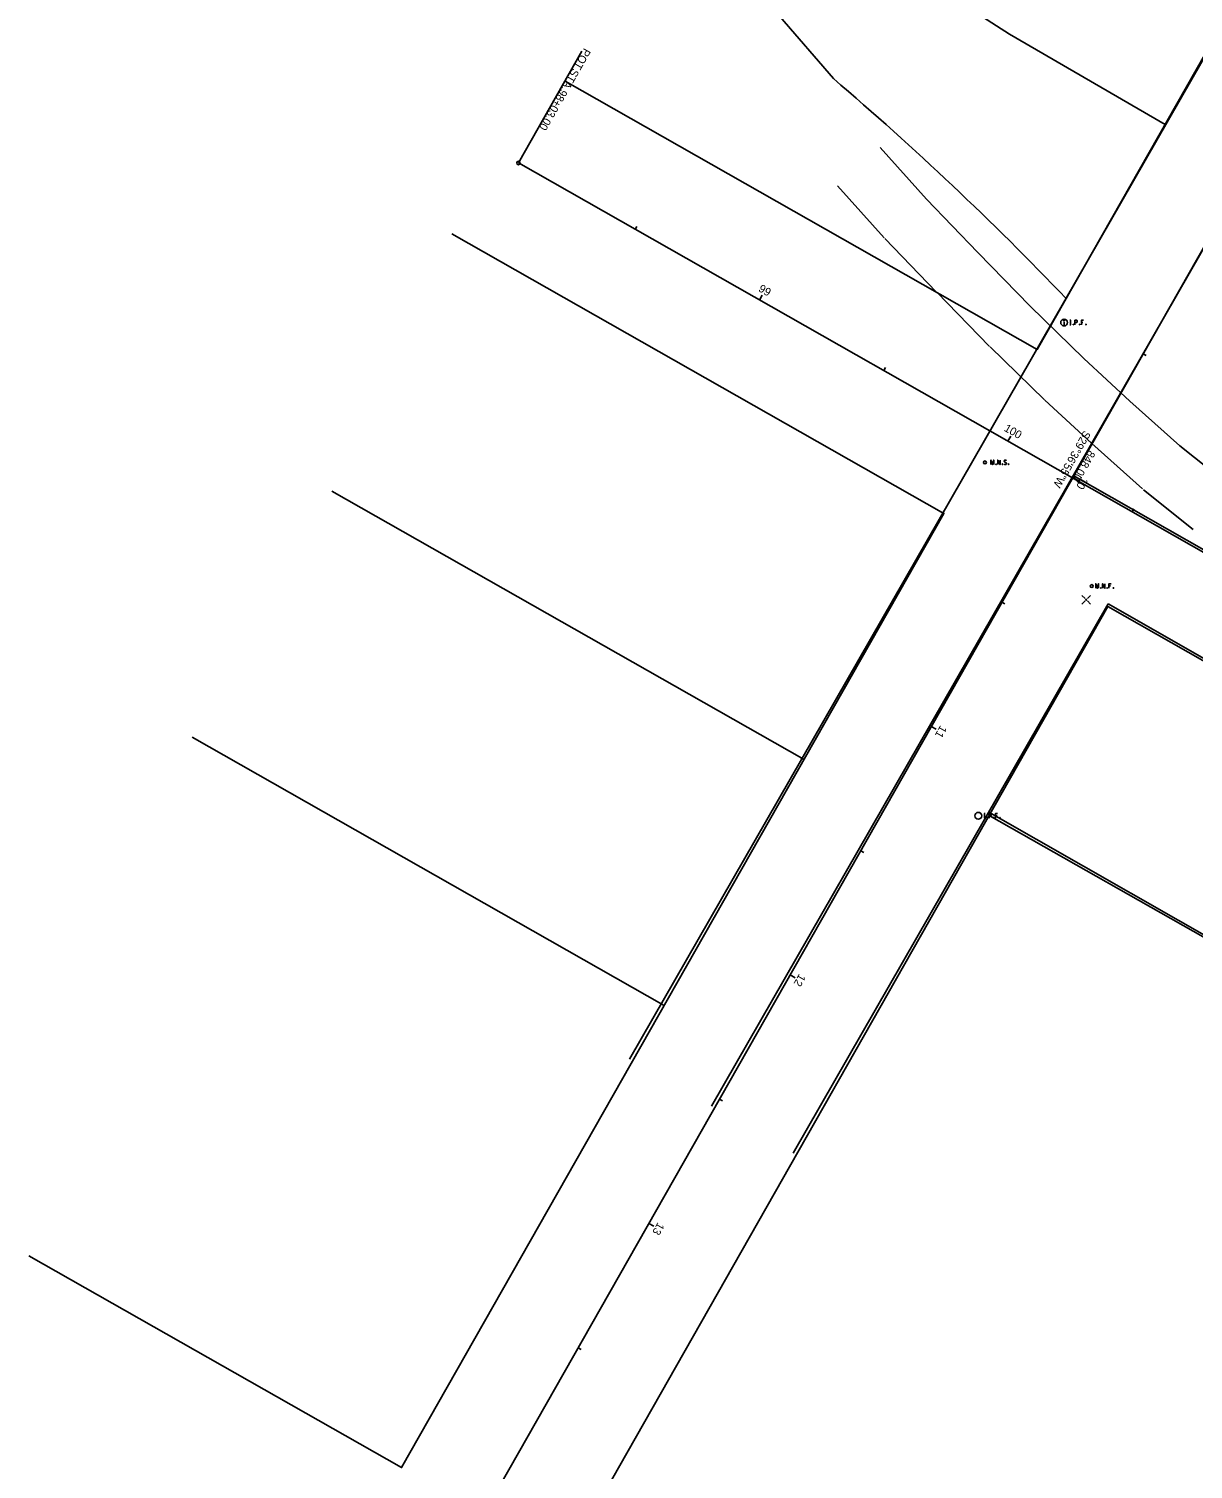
# Model space of a CAD drawing. Extents: x 119320 to 120701, y 385020 to 386199.
# Drawn here: x 119320 to 119728, y 385433 to 385937 of the extents above; entities that cross this region are included whole.
import ezdxf

# ---------------------------------------------------------------- set-up
doc = ezdxf.new("R2010")
doc.units = 0
for name, color, linetype in [('DV_X_Property_Line', 7, 'Continuous'), ('RW_X_CL', 7, 'Continuous'), ('RW_X_CL_100_Bearings', 7, 'Continuous'), ('RW_X_CL_100_Cardinal_Points', 7, 'Continuous'), ('RW_X_CL_100_Distances', 7, 'Continuous'), ('RW_X_CL_100_Stations', 7, 'Continuous'), ('RW_X_Esmt_RR', 7, 'Continuous'), ('RW_X_Fee_RW', 7, 'Continuous'), ('SC_Scratch1', 7, 'Continuous'), ('SV_P_Control_Cells_Set', 7, 'Continuous'), ('SV_X_Control_Cells_Found', 7, 'Continuous'), ('SV_X_Mon_Cells_Found', 7, 'Continuous')]:
    doc.layers.add(name, color=color, linetype=linetype)

msp = doc.modelspace()

# ---------------------------------------------------------------- linework, layer by layer
at = {"layer": 'DV_X_Property_Line'}
for p, q in [((119591.63, 385681.57), (119426.46, 385775.46)), ((119542.71, 385595.5), (119377.53, 385689.39)), ((119771.7, 385596.46), (119656.42, 385661.99))]:
    msp.add_line(p, q, dxfattribs=at)
msp.add_lwpolyline([(119601.86, 385919.77), (119583.12, 385941.5), (119603.33, 385973.97), (119663.5, 385935.28), (119717.9, 385903.69)], dxfattribs=at)
msp.add_arc((118870.1, 385063.6), 1126.28, 43.77787, 49.47989, dxfattribs=at)
at = {"layer": 'RW_X_CL'}
for p, q in [((119897.55, 386152.97), (119478.5, 385415.75)), ((119491.69, 385890.22), (120488.85, 385323.4))]:
    msp.add_line(p, q, dxfattribs=at)
at = {"layer": 'RW_X_CL_100_Cardinal_Points'}
msp.add_line((119491.69, 385890.22), (119513.92, 385929.34), dxfattribs=at)
msp.add_circle((119491.69, 385890.22), 0.6, dxfattribs=at)
at = {"layer": 'RW_X_CL_100_Stations'}
for p, q in [((119532.55, 385866.99), (119533.14, 385868.03)), ((119576.01, 385842.28), (119577, 385844.02)), ((119710.26, 385823.48), (119711.31, 385822.89)), ((119619.48, 385817.57), (119620.08, 385818.62)), ((119662.95, 385792.86), (119663.94, 385794.6)), ((119685.55, 385780.02), (119687.29, 385779.03)), ((119706.42, 385768.16), (119707.01, 385769.2)), ((119660.85, 385736.55), (119661.89, 385735.95)), ((119636.14, 385693.08), (119637.88, 385692.09)), ((119611.43, 385649.61), (119612.47, 385649.02)), ((119586.72, 385606.14), (119588.46, 385605.15)), ((119562.01, 385562.67), (119563.05, 385562.08)), ((119537.3, 385519.21), (119539.04, 385518.22)), ((119512.59, 385475.74), (119513.64, 385475.15))]:
    msp.add_line(p, q, dxfattribs=at)
at = {"layer": 'RW_X_Esmt_RR'}
for p, q in [((119618.22, 385895.61), (119634.45, 385877.51)), ((119603.33, 385882.25), (119619.68, 385864.02)), ((119634.45, 385877.51), (119652.36, 385858.93)), ((119619.93, 385863.76), (119637.98, 385845.03)), ((119652.36, 385858.93), (119670.73, 385840.1)), ((119638.02, 385844.99), (119656.51, 385826.04)), ((119670.73, 385840.1), (119689.55, 385821.79)), ((119656.69, 385825.86), (119675.69, 385807.36)), ((119689.55, 385821.79), (119705.64, 385806.91)), ((119675.88, 385807.19), (119692.13, 385792.17)), ((119705.64, 385806.91), (119723.13, 385791.28)), ((119692.25, 385792.06), (119710, 385776.19)), ((119723.13, 385791.28), (119740.18, 385777.58)), ((119710.4, 385775.85), (119727.7, 385761.95))]:
    msp.add_line(p, q, dxfattribs=at)
at = {"layer": 'RW_X_Fee_RW'}
for points in [[(119507.99, 385918.9), (119673.17, 385825.01), (119869.11, 386169.71), (119816.95, 386199.36)], [(119468.42, 385865.48), (119640.56, 385767.63), (119450.79, 385433.8), (119320.39, 385507.92)], [(119507.18, 385399.44), (119697.94, 385735.02), (120042.2, 385539.33), (119851.45, 385203.75), (119507.18, 385399.44)]]:
    msp.add_lwpolyline(points, dxfattribs=at)
at = {"layer": 'SC_Scratch1'}
for p, q in [((119530.56, 385576.63), (119762.43, 385980.86)), ((119559.19, 385560.21), (119791.06, 385964.44)), ((119685.77, 385780.89), (120087.8, 385551.87)), ((119587.81, 385543.79), (119698.02, 385735.93)), ((119698.02, 385735.93), (119813.24, 385670.29)), ((119656.23, 385663.06), (119828.3, 385565.04))]:
    msp.add_line(p, q, dxfattribs=at)
at = {"layer": 'SV_P_Control_Cells_Set'}
for points in [[(119657, 385784.69), (119657, 385786.29), (119657.51, 385784.69), (119657.99, 385786.29), (119657.99, 385784.69)], [(119659.37, 385784.69), (119659.37, 385786.29), (119660.2, 385784.69), (119660.2, 385786.29)], [(119662.35, 385786.18), (119662.33, 385786.21), (119662.29, 385786.23), (119662.19, 385786.27), (119662.07, 385786.29), (119661.98, 385786.29), (119661.95, 385786.29), (119661.81, 385786.26), (119661.69, 385786.18), (119661.61, 385786.08), (119661.59, 385785.98), (119661.59, 385785.9), (119661.61, 385785.8), (119661.7, 385785.71), (119662.3, 385785.34), (119662.36, 385785.29), (119662.38, 385785.24), (119662.4, 385785.16), (119662.4, 385785.08), (119662.39, 385785.01), (119662.38, 385784.96), (119662.36, 385784.89), (119662.34, 385784.84), (119662.31, 385784.81), (119662.28, 385784.77), (119662.25, 385784.74), (119662.2, 385784.72), (119662.17, 385784.71), (119662.07, 385784.69), (119661.92, 385784.69), (119661.82, 385784.72), (119661.68, 385784.81), (119661.59, 385784.88)], [(119658.77, 385784.91), (119658.82, 385784.91), (119658.85, 385784.88), (119658.89, 385784.83), (119658.89, 385784.77), (119658.85, 385784.72), (119658.82, 385784.69), (119658.77, 385784.69), (119658.73, 385784.72), (119658.7, 385784.77), (119658.7, 385784.83), (119658.73, 385784.88), (119658.77, 385784.91)], [(119660.98, 385784.91), (119661.04, 385784.91), (119661.07, 385784.88), (119661.1, 385784.83), (119661.1, 385784.77), (119661.07, 385784.72), (119661.04, 385784.69), (119660.98, 385784.69), (119660.95, 385784.72), (119660.91, 385784.77), (119660.91, 385784.83), (119660.95, 385784.88), (119660.98, 385784.91)], [(119663.16, 385784.91), (119663.22, 385784.91), (119663.25, 385784.88), (119663.28, 385784.83), (119663.28, 385784.77), (119663.25, 385784.72), (119663.22, 385784.69), (119663.16, 385784.69), (119663.13, 385784.72), (119663.1, 385784.77), (119663.1, 385784.83), (119663.13, 385784.88), (119663.16, 385784.91)]]:
    msp.add_lwpolyline(points, dxfattribs=at)
msp.add_circle((119654.91, 385785.49), 0.497, dxfattribs=at)
at = {"layer": 'SV_X_Control_Cells_Found'}
for p, q in [((119688.82, 385738.94), (119689.91, 385737.85)), ((119688.82, 385735.92), (119689.91, 385737.01)), ((119690.74, 385737.85), (119691.83, 385738.94)), ((119690.74, 385737.01), (119691.83, 385735.92))]:
    msp.add_line(p, q, dxfattribs=at)
for points in [[(119693.69, 385741.41), (119693.69, 385743.01), (119694.2, 385741.41), (119694.68, 385743.01), (119694.68, 385741.41)], [(119695.45, 385741.63), (119695.51, 385741.63), (119695.54, 385741.6), (119695.57, 385741.55), (119695.57, 385741.49), (119695.54, 385741.44), (119695.51, 385741.41), (119695.45, 385741.41), (119695.42, 385741.44), (119695.39, 385741.49), (119695.39, 385741.55), (119695.42, 385741.6), (119695.45, 385741.63)], [(119696.06, 385741.41), (119696.06, 385743.01), (119696.89, 385741.41), (119696.89, 385743.01)], [(119697.67, 385741.63), (119697.72, 385741.63), (119697.76, 385741.6), (119697.79, 385741.55), (119697.79, 385741.49), (119697.76, 385741.44), (119697.72, 385741.41), (119697.67, 385741.41), (119697.64, 385741.44), (119697.6, 385741.49), (119697.6, 385741.55), (119697.64, 385741.6), (119697.67, 385741.63)], [(119699.04, 385743.01), (119698.27, 385743.01), (119698.27, 385741.41)], [(119698.27, 385742.23), (119698.82, 385742.23)], [(119699.82, 385741.63), (119699.87, 385741.63), (119699.91, 385741.6), (119699.94, 385741.55), (119699.94, 385741.49), (119699.91, 385741.44), (119699.87, 385741.41), (119699.82, 385741.41), (119699.78, 385741.44), (119699.75, 385741.49), (119699.75, 385741.55), (119699.78, 385741.6), (119699.82, 385741.63)]]:
    msp.add_lwpolyline(points, dxfattribs=at)
for centre, radius in [((119692.25, 385742.22), 0.497), ((119690.33, 385737.44), 0.17)]:
    msp.add_circle(centre, radius, dxfattribs=at)
at = {"layer": 'SV_X_Mon_Cells_Found'}
msp.add_line((119682.61, 385834.53), (119682.61, 385833.65), dxfattribs=at)
for points in [[(119684.64, 385835.21), (119685, 385835.21)], [(119684.64, 385833.61), (119685, 385833.61)], [(119684.82, 385833.61), (119684.82, 385835.21)], [(119685.78, 385833.83), (119685.83, 385833.83), (119685.87, 385833.8), (119685.9, 385833.75), (119685.9, 385833.69), (119685.87, 385833.64), (119685.83, 385833.61), (119685.78, 385833.61), (119685.75, 385833.64), (119685.71, 385833.69), (119685.71, 385833.75), (119685.75, 385833.8), (119685.78, 385833.83)], [(119686.39, 385833.61), (119686.39, 385835.21), (119686.92, 385835.21), (119686.97, 385835.2), (119687.05, 385835.18), (119687.08, 385835.15), (119687.11, 385835.12), (119687.16, 385835.06), (119687.19, 385835), (119687.21, 385834.9), (119687.21, 385834.75), (119687.2, 385834.7), (119687.18, 385834.62), (119687.14, 385834.53), (119687.09, 385834.49), (119687.06, 385834.47), (119687, 385834.44), (119686.92, 385834.43), (119686.39, 385834.43)], [(119688.03, 385833.83), (119688.08, 385833.83), (119688.12, 385833.8), (119688.15, 385833.75), (119688.15, 385833.69), (119688.12, 385833.64), (119688.08, 385833.61), (119688.03, 385833.61), (119688, 385833.64), (119687.96, 385833.69), (119687.96, 385833.75), (119688, 385833.8), (119688.03, 385833.83)], [(119689.4, 385835.21), (119688.63, 385835.21), (119688.63, 385833.61)], [(119688.63, 385834.43), (119689.17, 385834.43)], [(119690.18, 385833.83), (119690.23, 385833.83), (119690.27, 385833.8), (119690.3, 385833.75), (119690.3, 385833.69), (119690.27, 385833.64), (119690.23, 385833.61), (119690.18, 385833.61), (119690.14, 385833.64), (119690.11, 385833.69), (119690.11, 385833.75), (119690.14, 385833.8), (119690.18, 385833.83)], [(119654.59, 385662.63), (119654.95, 385662.63)], [(119654.59, 385661.03), (119654.95, 385661.03)], [(119654.77, 385661.03), (119654.77, 385662.63)], [(119655.73, 385661.25), (119655.78, 385661.25), (119655.82, 385661.22), (119655.85, 385661.17), (119655.85, 385661.11), (119655.82, 385661.06), (119655.78, 385661.03), (119655.73, 385661.03), (119655.7, 385661.06), (119655.66, 385661.11), (119655.66, 385661.17), (119655.7, 385661.22), (119655.73, 385661.25)], [(119656.34, 385661.03), (119656.34, 385662.63), (119656.86, 385662.63), (119656.92, 385662.62), (119657, 385662.6), (119657.03, 385662.57), (119657.06, 385662.54), (119657.11, 385662.48), (119657.14, 385662.42), (119657.16, 385662.32), (119657.16, 385662.17), (119657.15, 385662.12), (119657.13, 385662.04), (119657.08, 385661.95), (119657.04, 385661.91), (119657.01, 385661.89), (119656.95, 385661.86), (119656.86, 385661.85), (119656.34, 385661.85)], [(119657.98, 385661.25), (119658.03, 385661.25), (119658.07, 385661.22), (119658.1, 385661.17), (119658.1, 385661.11), (119658.07, 385661.06), (119658.03, 385661.03), (119657.98, 385661.03), (119657.94, 385661.06), (119657.91, 385661.11), (119657.91, 385661.17), (119657.94, 385661.22), (119657.98, 385661.25)], [(119659.34, 385662.63), (119658.58, 385662.63), (119658.58, 385661.03)], [(119658.58, 385661.85), (119659.12, 385661.85)], [(119660.13, 385661.25), (119660.18, 385661.25), (119660.22, 385661.22), (119660.25, 385661.17), (119660.25, 385661.11), (119660.22, 385661.06), (119660.18, 385661.03), (119660.13, 385661.03), (119660.09, 385661.06), (119660.06, 385661.11), (119660.06, 385661.17), (119660.09, 385661.22), (119660.13, 385661.25)]]:
    msp.add_lwpolyline(points, dxfattribs=at)
for centre, radius in [((119682.61, 385834.41), 1.2), ((119682.61, 385835.06), 0.16), ((119652.58, 385661.83), 1.2)]:
    msp.add_circle(centre, radius, dxfattribs=at)

# ---------------------------------------------------------------- texts
at = {"layer": 'RW_X_CL_100_Bearings'}
msp.add_text('S29°36\'55"W', height=2.8, rotation=240.3847, dxfattribs=at).set_placement((119689.6, 385796.84))
at = {"layer": 'RW_X_CL_100_Cardinal_Points'}
for s, p in [('POT', (119514.69, 385930.61)), (' STA. ', (119511.17, 385924.41)), ('98+03.00', (119506.56, 385916.31))]:
    msp.add_text(s, height=2.8, rotation=240.3847, dxfattribs=at).set_placement(p)
at = {"layer": 'RW_X_CL_100_Distances'}
msp.add_text("848.00'", height=2.8, rotation=240.3847, dxfattribs=at).set_placement((119691.24, 385789.94))
at = {"layer": 'RW_X_CL_100_Stations'}
for s, rotation, p in [('99', 330.3847, (119575.42, 385845.5)), ('100', 330.3847, (119661.35, 385796.65)), ('10', 240.3847, (119688.79, 385780.65)), ('11', 240.3847, (119639.35, 385693.67)), ('12', 240.3847, (119589.93, 385606.73)), ('13', 240.3847, (119540.5, 385519.78))]:
    msp.add_text(s, height=2.8, rotation=rotation, dxfattribs=at).set_placement(p)

doc.saveas('drawing.dxf')
